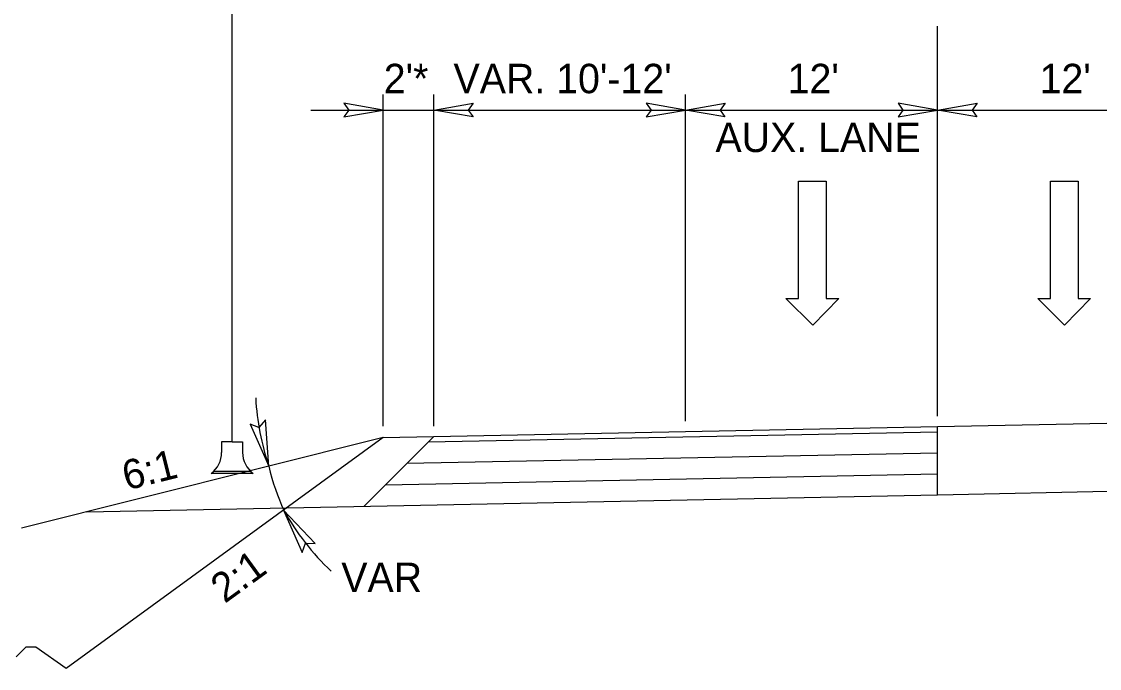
# Model space of a CAD drawing. Extents: x 1726582 to 1728895, y 538986 to 541550.
# Drawn here: x 1727008.5 to 1727265.4, y 541267.5 to 541421.5 of the extents above; entities that cross this region are included whole.
import ezdxf

# ---------------------------------------------------------------- set-up
doc = ezdxf.new("R2010")
doc.units = 0
for name, color, linetype in [('Default', 7, 'Continuous'), ('GSExisting', 7, 'Continuous'), ('GSProposed', 7, 'Continuous'), ('GSRelocate', 7, 'Continuous'), ('GSReplace', 7, 'Continuous')]:
    doc.layers.add(name, color=color, linetype=linetype)

msp = doc.modelspace()

# ---------------------------------------------------------------- linework, layer by layer
at = {"layer": 'Default'}
for p, q in [((1727058.65, 541321.41), (1727058.65, 541482.6)), ((1727226.79, 541327.57), (1727226.79, 541420.48)), ((1727094.68, 541325.17), (1727094.68, 541404.16)), ((1727106.69, 541325.17), (1727106.69, 541404.16)), ((1727166.74, 541326.37), (1727166.74, 541404.16)), ((1727226.79, 541327.57), (1727226.79, 541404.16)), ((1727106.69, 541325.17), (1727106.69, 541402.96)), ((1727077.42, 541400.46), (1727106.8, 541400.46)), ((1727106.8, 541400.46), (1727166.85, 541400.46)), ((1727166.85, 541400.46), (1727226.89, 541400.46)), ((1727226.89, 541400.46), (1727286.94, 541400.46)), ((1727193.63, 541355.56), (1727193.63, 541383.56)), ((1727193.63, 541383.56), (1727200.23, 541383.56)), ((1727200.23, 541383.56), (1727200.23, 541355.56)), ((1727253.68, 541355.56), (1727253.68, 541383.56)), ((1727253.68, 541383.56), (1727260.28, 541383.56)), ((1727260.28, 541383.56), (1727260.28, 541355.56)), ((1727197.03, 541349.26), (1727190.63, 541355.56)), ((1727190.63, 541355.56), (1727193.63, 541355.56)), ((1727203.23, 541355.56), (1727197.03, 541349.26)), ((1727200.23, 541355.56), (1727203.23, 541355.56)), ((1727257.08, 541349.26), (1727250.68, 541355.56)), ((1727250.68, 541355.56), (1727253.68, 541355.56)), ((1727263.28, 541355.56), (1727257.08, 541349.26)), ((1727260.28, 541355.56), (1727263.28, 541355.56)), ((1727058.65, 541321.41), (1727056.15, 541321.41)), ((1727056.15, 541321.41), (1727056.15, 541318.91)), ((1727058.65, 541321.41), (1727061.15, 541321.41)), ((1727061.15, 541321.41), (1727061.15, 541318.91)), ((1727063.65, 541313.91), (1727053.65, 541313.91)), ((1727063.07, 541314.41), (1727054.24, 541314.41))]:
    msp.add_line(p, q, dxfattribs=at)
for points in [[(1727085.3, 541398.85), (1727094.68, 541400.46), (1727085.25, 541402.13), (1727086.45, 541400.46)], [(1727116.07, 541398.85), (1727106.69, 541400.46), (1727116.12, 541402.13), (1727114.92, 541400.46)], [(1727157.36, 541398.85), (1727166.74, 541400.46), (1727157.31, 541402.13), (1727158.51, 541400.46)], [(1727176.12, 541398.85), (1727166.74, 541400.46), (1727176.17, 541402.13), (1727174.97, 541400.46)], [(1727217.41, 541398.85), (1727226.79, 541400.46), (1727217.36, 541402.13), (1727218.55, 541400.46)], [(1727236.16, 541398.85), (1727226.79, 541400.46), (1727236.22, 541402.13), (1727235.02, 541400.46)], [(1727062.93, 541325.66), (1727067.38, 541315.63), (1727066.58, 541326.64), (1727065.05, 541324.83)], [(1727078.46, 541297.21), (1727070.93, 541305.19), (1727075.35, 541295.07), (1727076.18, 541297.28)], [(1727078.46, 541297.21), (1727070.93, 541305.19), (1727075.35, 541295.07), (1727076.18, 541297.28)]]:
    msp.add_lwpolyline(points, close=True, dxfattribs=at)
for centre, start, end in [((1727049.9, 541318.91), 306.8699, 0), ((1727067.4, 541318.91), 180, 233.1301)]:
    msp.add_arc(centre, 6.25, start, end, dxfattribs=at)
at = {"layer": 'GSExisting'}
msp.add_lwpolyline([(1727019.07, 541267.47), (1727011.86, 541272.53), (1727009.52, 541272.53), (1727007.18, 541270.21)], dxfattribs=at)
for centre, start, end in [((1727124.55, 541334.97), 182.9343, 198.686), ((1727123.68, 541334.52), 209.0778, 226.6941), ((1727123.68, 541334.52), 209.0778, 226.6941)]:
    msp.add_arc(centre, 60.35, start, end, dxfattribs=at)
msp.add_ellipse((1727096.27, 541350.06), major_axis=(-9.27, -59.64), ratio=0.5, start_param=5.403228, end_param=5.638322, dxfattribs=at)
at = {"layer": 'GSReplace'}
for p, q in [((1727226.79, 541325.1), (1727461.04, 541329.79)), ((1727094.68, 541322.46), (1727226.76, 541325.1)), ((1727105.41, 541321.42), (1727226.79, 541323.85)), ((1727226.79, 541308.85), (1727226.79, 541325.1)), ((1727094.68, 541322.46), (1727008.46, 541300.91)), ((1727094.68, 541322.46), (1727019.07, 541267.47)), ((1727106.69, 541322.7), (1727090.1, 541306.11)), ((1727100.31, 541316.32), (1727226.79, 541318.85)), ((1727095.21, 541311.22), (1727226.79, 541313.85)), ((1727226.79, 541308.85), (1727461.04, 541313.53)), ((1727024, 541304.79), (1727226.79, 541308.85))]:
    msp.add_line(p, q, dxfattribs=at)

# ---------------------------------------------------------------- texts
at = {"layer": 'GSProposed'}
for s, height, p in [("2'*", 7.005, (1727094.79, 541404.47)), ("VAR. 10'-12'", 7.0055, (1727111.42, 541404.47)), ("12'", 7.005, (1727191.06, 541404.47)), ("12'", 7.005, (1727251.11, 541404.47)), ('AUX. LANE', 7.005, (1727173.85, 541390.46))]:
    msp.add_text(s, height=height, dxfattribs=at).set_placement(p)
at = {"layer": 'GSRelocate'}
for s, rotation, p in [('6:1', 14.0362, (1727033.49, 541309.84)), ('2:1', 36.0298, (1727056.88, 541282.8))]:
    msp.add_text(s, height=7.005, rotation=rotation, dxfattribs=at).set_placement(p)
msp.add_text('VAR', height=7.005, dxfattribs=at).set_placement((1727084.67, 541285.66))

doc.saveas('drawing.dxf')
